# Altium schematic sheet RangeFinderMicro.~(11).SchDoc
size A; DocumentNumber: 2; SheetNumber: 2; SheetTotal: 6
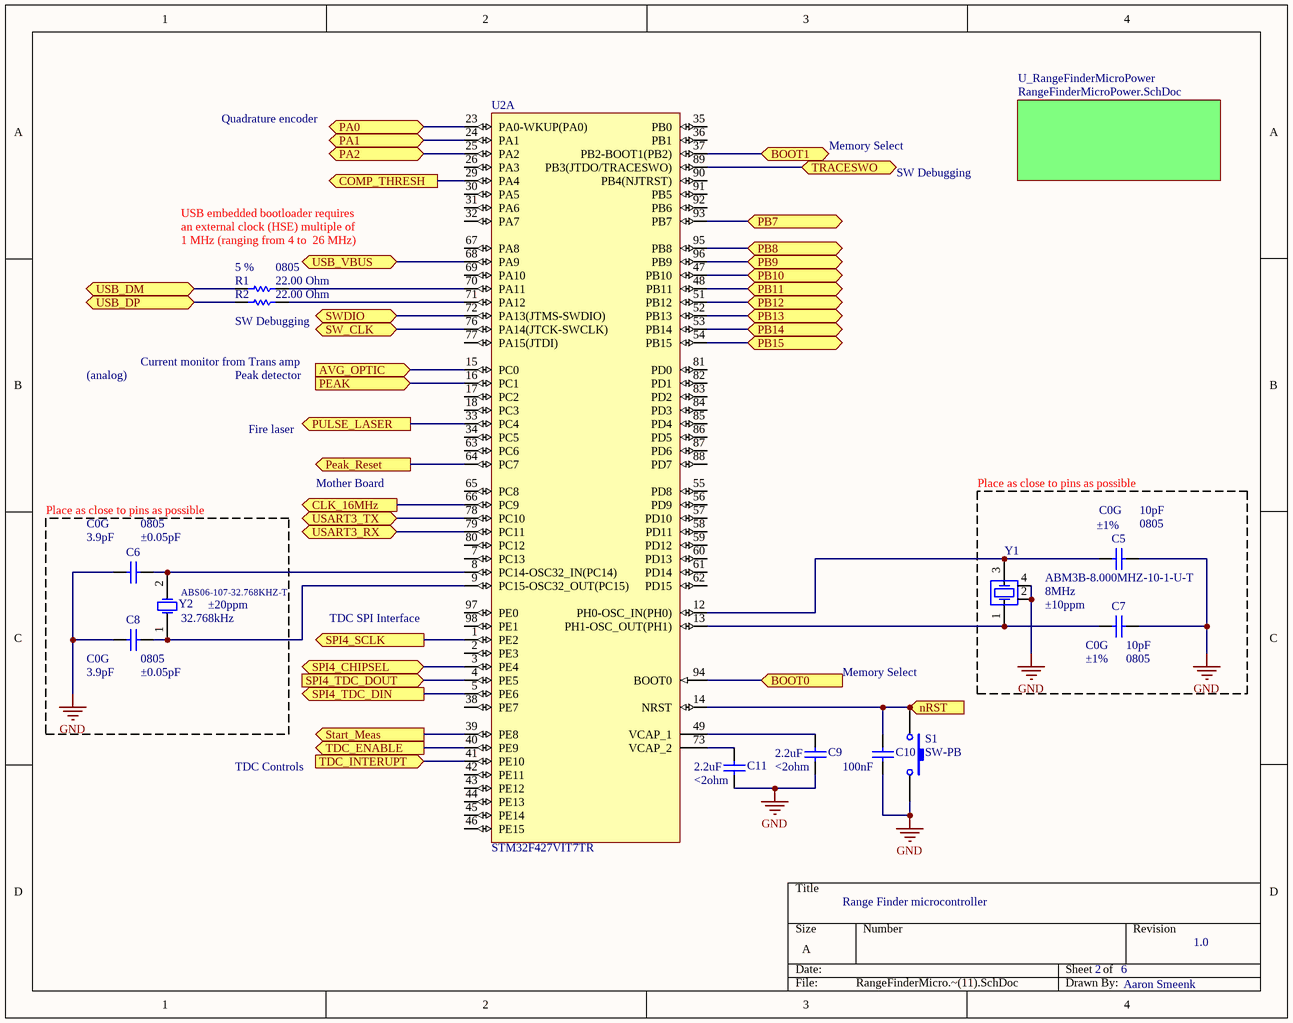
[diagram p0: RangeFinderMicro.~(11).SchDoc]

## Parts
C5  value 10pF  Tolerance: ±1%  Case-EIA: 0805  Temperature Coefficient: C0G  [CAPC0805(2012)100_M]  (hidden comment: CAP 10pF 10V 0805(2012))
C6  value 3.9pF  Case-EIA: 0805  Tolerance: ±0.05pF  Temperature Coefficient: C0G  [CAPC0805(2012)75_L]  (hidden comment: CAP 3.9pF 10V 0805(2012))
C7  value 10pF  Tolerance: ±1%  Case-EIA: 0805  Temperature Coefficient: C0G  [CAPC0805(2012)100_M]  (hidden comment: CAP 10pF 10V 0805(2012))
C8  value 3.9pF  Case-EIA: 0805  Tolerance: ±0.05pF  Temperature Coefficient: C0G  [CAPC0805(2012)75_L]  (hidden comment: CAP 3.9pF 10V 0805(2012))
C9  value 2.2uF  ESR: <2ohm  [CAPC0805(2012)145_M]  (hidden comment: CAP 1.5uF 6.3V 0805(2012))
C10  value 100nF  [CAPC0805(2012)145_M]  (hidden comment: CAP 100nF 0805(2012))
C11  value 2.2uF  ESR: <2ohm  [CAPC0805(2012)145_M]  (hidden comment: CAP 1.5uF 6.3V 0805(2012))
R1  value 22.00 Ohm  Tolerance: 5 %  Case-EIA: 0805  [RESC0805(2012)_M]  (hidden comment: 22R 5% 0805(2012))
R2  value 22.00 Ohm  [RESC0805(2012)_M]  (hidden comment: 22R 5% 0805(2012))
S1  SW-PB  [SPST-2]
U2  STM32F427VIT7TR  [STM-LQFP100_N]  (part A of 2)
Y1  ABM3B-8.000MHZ-10-1-U-T  Frequency: 8MHz  Frequency Stability: ±10ppm  [ABM3B Series]
Y2  ABS06-107-32.768KHZ-T  Frequency: 32.768kHz  Frequency Tolerance: ±20ppm  [ABS06-107]

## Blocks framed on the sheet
Place as close to pins as possible: C5 C7 Y1
Place as close to pins as possible: C6 C8 Y2

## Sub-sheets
U_RangeFinderMicroPower = RangeFinderMicroPower.SchDoc: no entries

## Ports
AVG_OPTIC (in), BOOT0 (in), BOOT1, CLK_16MHz (out), COMP_THRESH (out), nRST (in), PA0 (bidir), PA1 (bidir), PA2 (bidir), PB7 (bidir), PB8 (bidir), PB9 (bidir), PB10 (bidir), PB11 (bidir), PB12 (bidir), PB13 (bidir), PB14 (bidir), PB15 (bidir), PEAK (in), Peak_Reset (out), PULSE_LASER (out), SPI4_CHIPSEL, SPI4_SCLK (out), SPI4_TDC_DIN (out), SPI4_TDC_DOUT (in), Start_Meas (out), SW_CLK, SWDIO, TDC_ENABLE (out), TDC_INTERUPT (in), TRACESWO, USART3_RX, USART3_TX, USB_DM, USB_DP, USB_VBUS

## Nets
GND: C5.2 C6.1 C7.2 C8.1 C9.1 C10.1 C11.1 S1.2 Y1.2 Y1.4
AVG_OPTIC: U2.15(PC0) ; port AVG_OPTIC
BOOT0: U2.94(BOOT0) ; port BOOT0
BOOT1: U2.37(PB2-BOOT1(PB2)) ; port BOOT1
CLK_16MHz: U2.66(PC9) ; port CLK_16MHz
COMP_THRESH: U2.29(PA4) ; port COMP_THRESH
nRST: C10.2 S1.1 U2.14(NRST) ; port nRST
PA0: U2.23(PA0-WKUP(PA0)) ; port PA0
PA1: U2.24(PA1) ; port PA1
PA2: U2.25(PA2) ; port PA2
PB7: U2.93(PB7) ; port PB7
PB8: U2.95(PB8) ; port PB8
PB9: U2.96(PB9) ; port PB9
PB10: U2.47(PB10) ; port PB10
PB11: U2.48(PB11) ; port PB11
PB12: U2.51(PB12) ; port PB12
PB13: U2.52(PB13) ; port PB13
PB14: U2.53(PB14) ; port PB14
PB15: U2.54(PB15) ; port PB15
PEAK: U2.16(PC1) ; port PEAK
Peak_Reset: U2.64(PC7) ; port Peak_Reset
PULSE_LASER: U2.33(PC4) ; port PULSE_LASER
SPI4_CHIPSEL: U2.3(PE4) ; port SPI4_CHIPSEL
SPI4_SCLK: U2.1(PE2) ; port SPI4_SCLK
SPI4_TDC_DIN: U2.5(PE6) ; port SPI4_TDC_DIN
SPI4_TDC_DOUT: U2.4(PE5) ; port SPI4_TDC_DOUT
Start_Meas: U2.39(PE8) ; port Start_Meas
SW_CLK: U2.76(PA14(JTCK-SWCLK)) ; port SW_CLK
SWDIO: U2.72(PA13(JTMS-SWDIO)) ; port SWDIO
TDC_ENABLE: U2.40(PE9) ; port TDC_ENABLE
TDC_INTERUPT: U2.41(PE10) ; port TDC_INTERUPT
TRACESWO: U2.89(PB3(JTDO/TRACESWO)) ; port TRACESWO
USART3_RX: U2.79(PC11) ; port USART3_RX
USART3_TX: U2.78(PC10) ; port USART3_TX
USB_DM: R1.1 ; port USB_DM
USB_DP: R2.1 ; port USB_DP
USB_VBUS: U2.68(PA9) ; port USB_VBUS
NetC5_1: C5.1 U2.12(PH0-OSC_IN(PH0)) Y1.3
NetC6_2: C6.2 U2.8(PC14-OSC32_IN(PC14)) Y2.2
NetC7_1: C7.1 U2.13(PH1-OSC_OUT(PH1)) Y1.1
NetC8_2: C8.2 U2.9(PC15-OSC32_OUT(PC15)) Y2.1
NetC9_2: C9.2 U2.49(VCAP_1)
NetC11_2: C11.2 U2.73(VCAP_2)
NetR1_2: R1.2 U2.70(PA11)
NetR2_2: R2.2 U2.71(PA12)

Not connected (* = marked no-connect by the designer): U2 2(PE3) 7(PC13) 17(PC2) 18(PC3) 26(PA3) 30(PA5) 31(PA6) 32(PA7) 34(PC5) 35(PB0) 36(PB1) 38(PE7) 42(PE11) 43(PE12) 44(PE13) 45(PE14) 46(PE15) 55(PD8) 56(PD9) 57(PD10) 58(PD11) 59(PD12) 60(PD13) 61(PD14) 62(PD15) 63(PC6) 65(PC8) 67(PA8) 69(PA10) 77(PA15(JTDI)) 80(PC12) 81(PD0) 82(PD1) 83(PD2) 84(PD3) 85(PD4) 86(PD5) 87(PD6) 88(PD7) 90(PB4(NJTRST)) 91(PB5) 92(PB6) 97(PE0) 98(PE1)

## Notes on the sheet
- Quadrature encoder
- Memory Select
- USB embedded bootloader requires
- an external clock (HSE) multiple of
- SW Debugging
- 1 MHz (ranging from 4 to  26 MHz)
- Current monitor from Trans amp
- (near R2) SW Debugging
- (analog)
- Peak detector
- Fire laser
- Mother Board
- TDC SPI Interface
- TDC Controls
- Range Finder microcontroller
- 2
- 6
- 1.0
- Aaron Smeenk

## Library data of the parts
C5 C7 = CMP-1036-00821-1: CAP 10pF 10V ±0.25pF 0805 (2012 Metric) Thickness 1mm SMD; Case-Metric: 2012
C6 C8 = CMP-1036-00455-1: CAP 3.9pF 10V ±0.1pF 0805 (2012 Metric) Thickness 0.75mm SMD; Manufacturer Part Number: GRM1555C1H4R0WA01D; Case-Metric: 2012
C9 C11 = CMP-1036-04784-1: CAP 1.5uF 6.3V ±20% 0805 (2012 Metric) Thickness 1.45mm SMD; Case-EIA: 0805; Case-Metric: 2012
C10 = CMP-1036-04784-1: CAP 1.5uF 6.3V ±20% 0805 (2012 Metric) Thickness 1.45mm SMD; Case-EIA: 0805; Case-Metric: 2012; ESR: <2ohm
R1 = CMP-1013-00034-1: 22R 0.125W 5% 0805 (2012 Metric)  SMD; Case-Metric: 2012
R2 = CMP-1013-00034-1: 22R 0.125W 5% 0805 (2012 Metric)  SMD; Case-Metric: 2012; Case-EIA: 0805
S1 = SW-PB: Switch
U2 = CMP-0243-00026-2: ARM Cortex-M4 32-bit MCU+FPU, 210 DMIPS, 2048 kB Flash, 256 kB Internal RAM, 82 I/Os, 100-pin LQFP, -40 to 105 degC, Tape and Reel; Manufacturer: STMicroelectronics; Supply Voltage(Vcc) max (V): 3.6; Supply Voltage(Vcc) min (V): 1.8; FLASH Size (Prog) (kB): 2048; Operating Frequency(F) (Processor speed) (MHz): 168; D/A Converter: 2x12-bit; Internal RAM Size (kB): 256; I/Os (High Current): 82
Y1 = ABM3B Series: CRYSTAL 8MHZ 10PF SMD; ESR (Equivalent Series Resistance): 200 Ohm; Operating Mode: Fundamental
Y2 = ABS06-107: CRYSTAL 32.768 KHZ 4PF SMD; ESR (Equivalent Series Resistance): 60 kOhm; Operating Mode: Fundamental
